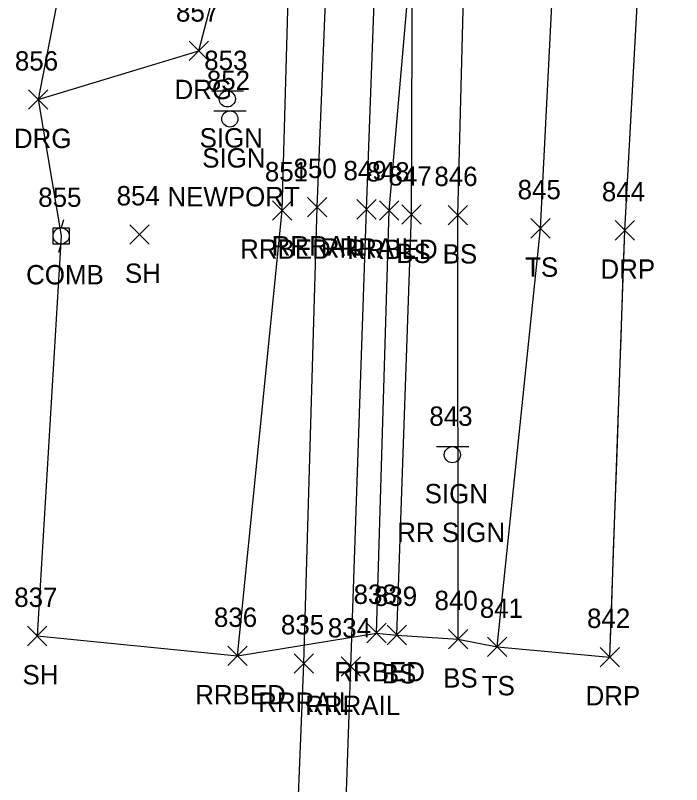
# Model space of a CAD drawing. Extents: x 1715662 to 1717487, y 887396 to 890004.
# Drawn here: x 1716428.2 to 1716497, y 887898 to 887977.4 of the extents above; entities that cross this region are included whole.
import ezdxf

# ---------------------------------------------------------------- set-up
doc = ezdxf.new("R2010")
doc.units = 0
for name, color, linetype in [('L_A', 7, 'Continuous'), ('L_I', 7, 'Continuous'), ('L_TIC', 7, 'Continuous'), ('LELB', 7, 'Continuous'), ('LSOGP', 7, 'Continuous'), ('R_A', 7, 'Continuous'), ('R_I', 7, 'Continuous'), ('R_TIC', 7, 'Continuous'), ('RDG', 7, 'Continuous'), ('RDP', 7, 'Continuous'), ('RR', 7, 'Continuous'), ('RRB', 7, 'Continuous'), ('S_A', 7, 'Continuous'), ('S_C', 7, 'Continuous'), ('S_I', 7, 'Continuous'), ('SSGN', 7, 'Continuous'), ('U_A', 7, 'Continuous'), ('U_I', 7, 'Continuous'), ('UP', 7, 'Continuous')]:
    doc.layers.add(name, color=color, linetype=linetype)

msp = doc.modelspace()

# ---------------------------------------------------------------- linework, layer by layer
at = {"layer": 'L_TIC'}
for points in [[(1716468.101, 887955.83), (1716470.101, 887957.83)], [(1716470.101, 887955.83), (1716468.101, 887957.83)], [(1716472.886, 887955.779), (1716474.886, 887957.779)], [(1716474.886, 887955.779), (1716472.886, 887957.779)], [(1716481.429, 887954.414), (1716483.429, 887956.414)], [(1716483.429, 887954.414), (1716481.429, 887956.414)], [(1716440.018, 887953.781), (1716442.018, 887955.781)], [(1716442.018, 887953.781), (1716440.018, 887955.781)], [(1716429.444, 887912.327), (1716431.444, 887914.327)], [(1716431.444, 887912.327), (1716429.444, 887914.327)], [(1716466.596, 887912.429), (1716468.596, 887914.429)], [(1716468.596, 887912.429), (1716466.596, 887914.429)], [(1716472.935, 887911.997), (1716474.935, 887913.997)], [(1716474.935, 887911.997), (1716472.935, 887913.997)], [(1716476.957, 887911.196), (1716478.957, 887913.196)], [(1716478.957, 887911.196), (1716476.957, 887913.196)]]:
    msp.add_lwpolyline(points, dxfattribs=at)
at = {"layer": 'LELB'}
for points in [[(1716473.935, 887912.997), (1716473.886, 887956.779), (1716474.684, 887987.259), (1716479.04, 888013.684), (1716476.318, 888035.409), (1716482.255, 888066.146), (1716480.224, 888093.78), (1716481.354, 888116.759), (1716483.546, 888136.5), (1716484.284, 888166.833)], [(1716467.596, 887913.429), (1716469.101, 887956.83), (1716469.216, 887985.005), (1716470.422, 888014.281), (1716470.937, 888035.677), (1716470.666, 888066.826)], [(1716477.957, 887912.196), (1716482.429, 887955.414), (1716483.839, 887983.248), (1716484.191, 888013.31), (1716484.915, 888034.821), (1716482.255, 888066.146)]]:
    msp.add_lwpolyline(points, dxfattribs=at)
at = {"layer": 'LSOGP'}
msp.add_lwpolyline([(1716434.424, 887988.776), (1716430.567, 887968.704), (1716432.923, 887954.625), (1716430.445, 887913.326), (1716451.125, 887911.268), (1716465.492, 887913.635), (1716467.599, 887913.425), (1716473.937, 887912.992), (1716477.96, 887912.2), (1716489.598, 887911.149), (1716489.79, 887916.656), (1716489.981, 887922.163), (1716490.173, 887927.67), (1716490.365, 887933.177), (1716490.556, 887938.684), (1716490.748, 887944.191), (1716490.94, 887949.698), (1716491.131, 887955.205), (1716491.515, 887962.117), (1716491.899, 887969.03), (1716492.284, 887975.943), (1716492.668, 887982.855)], dxfattribs=at)
at = {"layer": 'R_TIC'}
for points in [[(1716446.147, 887972.755), (1716448.147, 887974.755)], [(1716448.147, 887972.755), (1716446.147, 887974.755)], [(1716429.565, 887967.701), (1716431.565, 887969.701)], [(1716431.565, 887967.701), (1716429.565, 887969.701)], [(1716454.759, 887956.269), (1716456.759, 887958.269)], [(1716456.759, 887956.269), (1716454.759, 887958.269)], [(1716458.375, 887956.606), (1716460.375, 887958.606)], [(1716460.375, 887956.606), (1716458.375, 887958.606)], [(1716463.449, 887956.376), (1716465.449, 887958.376)], [(1716465.449, 887956.376), (1716463.449, 887958.376)], [(1716465.807, 887956.247), (1716467.807, 887958.247)], [(1716467.807, 887956.247), (1716465.807, 887958.247)], [(1716490.13, 887954.207), (1716492.13, 887956.207)], [(1716492.13, 887954.207), (1716490.13, 887956.207)], [(1716464.489, 887912.634), (1716466.489, 887914.634)], [(1716466.489, 887912.634), (1716464.489, 887914.634)], [(1716450.122, 887910.264), (1716452.122, 887912.264)], [(1716452.122, 887910.264), (1716450.122, 887912.264)], [(1716488.596, 887910.153), (1716490.596, 887912.153)], [(1716490.596, 887910.153), (1716488.596, 887912.153)], [(1716456.985, 887909.493), (1716458.985, 887911.493)], [(1716458.985, 887909.493), (1716456.985, 887911.493)], [(1716461.83, 887909.171), (1716463.83, 887911.171)], [(1716463.83, 887909.171), (1716461.83, 887911.171)]]:
    msp.add_lwpolyline(points, dxfattribs=at)
at = {"layer": 'RDG'}
msp.add_lwpolyline([(1716430.565, 887968.701), (1716447.147, 887973.755), (1716451.126, 887989.049), (1716451.206, 888015.403), (1716452.793, 888038.08), (1716450.596, 888065.72), (1716449.432, 888091.878), (1716428.67, 888089.543)], dxfattribs=at)
at = {"layer": 'RDP'}
msp.add_lwpolyline([(1716489.596, 887911.153), (1716491.13, 887955.207), (1716492.666, 887982.856), (1716493.215, 888012.901), (1716493.045, 888035.082), (1716494.671, 888064.725)], dxfattribs=at)
at = {"layer": 'RR'}
for points in [[(1716461.974, 887885.395), (1716462.83, 887910.171), (1716464.449, 887957.376), (1716465.442, 887984.3), (1716466.282, 888014.511), (1716466.758, 888036.126), (1716467.795, 888066.641), (1716468.474, 888094.515), (1716469.094, 888116.578), (1716469.786, 888136.617), (1716470.876, 888167.552), (1716471.475, 888180.714), (1716472.375, 888199.713), (1716473.429, 888217.51), (1716474.73, 888238.997), (1716477.211, 888271.313), (1716478.99, 888290.556), (1716481.768, 888315.217), (1716484.181, 888333.138), (1716487.83, 888360.815), (1716492.094, 888386.989), (1716497.003, 888416.355)], [(1716440.969, 887401.259), (1716441.928, 887429.633), (1716442.727, 887457.662), (1716443.78, 887486.944), (1716444.743, 887516.479), (1716445.823, 887546.3), (1716446.812, 887576.054), (1716447.839, 887605.656), (1716448.734, 887635.174), (1716449.755, 887664.736), (1716450.806, 887693.868), (1716451.722, 887723.384), (1716452.665, 887753.08), (1716453.616, 887781.945), (1716454.514, 887808.71), (1716455.264, 887837.152), (1716456.132, 887864.63), (1716456.985, 887885.763), (1716457.985, 887910.493), (1716459.375, 887957.606), (1716460.393, 887983.057)]]:
    msp.add_lwpolyline(points, dxfattribs=at)
at = {"layer": 'RRB'}
for points in [[(1716451.122, 887911.264), (1716455.759, 887957.269), (1716456.57, 887986.491), (1716457.287, 888015.179), (1716457.426, 888037.571), (1716455.225, 888065.723), (1716453.695, 888095.105), (1716450.491, 888116.185), (1716448.524, 888137.034), (1716442.327, 888164.475), (1716438.205, 888182.393), (1716431.513, 888203.116)], [(1716465.489, 887913.634), (1716466.807, 887957.247), (1716469.216, 887985.005), (1716468.759, 888014.221), (1716469.282, 888035.906), (1716469.733, 888066.764), (1716471.504, 888094.677)]]:
    msp.add_lwpolyline(points, dxfattribs=at)
at = {"layer": 'SSGN'}
for p, q in [((1716448.436, 887969.61), (1716451.769, 887969.61)), ((1716450.083, 887968.776), (1716450.083, 887968.776)), ((1716448.705, 887967.54), (1716452.038, 887967.54)), ((1716450.351, 887966.707), (1716450.351, 887966.707)), ((1716471.682, 887932.876), (1716475.015, 887932.876)), ((1716473.329, 887932.042), (1716473.329, 887932.042))]:
    msp.add_line(p, q, dxfattribs=at)
for centre in [(1716450.083, 887968.776), (1716450.351, 887966.707), (1716473.329, 887932.042)]:
    msp.add_circle(centre, 0.833, dxfattribs=at)
at = {"layer": 'UP'}
for p, q in [((1716433.17, 887956.296), (1716432.92, 887955.462)), ((1716432.087, 887953.796), (1716432.087, 887955.462)), ((1716432.087, 887955.462), (1716433.754, 887955.462)), ((1716433.754, 887955.462), (1716433.754, 887953.796)), ((1716432.92, 887954.629), (1716432.92, 887954.629)), ((1716433.754, 887953.796), (1716432.087, 887953.796)), ((1716432.67, 887952.962), (1716432.92, 887953.796))]:
    msp.add_line(p, q, dxfattribs=at)
msp.add_circle((1716432.92, 887954.629), 0.833, dxfattribs=at)

# ---------------------------------------------------------------- texts
at = {"layer": 'L_A'}
for s, p in [('BS', (1716467.541, 887951.83)), ('BS', (1716472.327, 887951.779)), ('TS', (1716480.839, 887950.414)), ('SH', (1716439.506, 887949.781)), ('SH', (1716428.932, 887908.327)), ('BS', (1716466.037, 887908.429)), ('BS', (1716472.376, 887907.997)), ('TS', (1716476.367, 887907.196))]:
    msp.add_text(s, height=2, dxfattribs=at).set_placement(p)
at = {"layer": 'L_I'}
for s, p in [('847', (1716466.738, 887959.83)), ('846', (1716471.469, 887959.779)), ('845', (1716480.067, 887958.414)), ('854', (1716438.655, 887957.781)), ('837', (1716428.082, 887916.327)), ('839', (1716465.226, 887916.429)), ('840', (1716471.486, 887915.997)), ('841', (1716476.162, 887915.196))]:
    msp.add_text(s, height=2, dxfattribs=at).set_placement(p)
at = {"layer": 'R_A'}
for s, p in [('DRG', (1716444.635, 887968.755)), ('DRG', (1716428.053, 887963.701)), ('RRBED', (1716451.405, 887952.269)), ('RRRAIL', (1716454.666, 887952.606)), ('RRRAIL', (1716459.74, 887952.376)), ('RRBED', (1716462.453, 887952.247)), ('DRP', (1716488.618, 887950.207)), ('RRBED', (1716461.135, 887908.634)), ('RRBED', (1716446.768, 887906.264)), ('DRP', (1716487.084, 887906.153)), ('RRRAIL', (1716453.276, 887905.493)), ('RRRAIL', (1716458.122, 887905.171))]:
    msp.add_text(s, height=2, dxfattribs=at).set_placement(p)
at = {"layer": 'R_I'}
for s, p in [('857', (1716444.784, 887976.755)), ('856', (1716428.148, 887971.701)), ('850', (1716456.926, 887960.606)), ('851', (1716453.964, 887960.269)), ('849', (1716462.079, 887960.376)), ('848', (1716464.445, 887960.247)), ('844', (1716488.768, 887958.207)), ('838', (1716463.127, 887916.634)), ('836', (1716448.705, 887914.264)), ('842', (1716487.234, 887914.153)), ('835', (1716455.622, 887913.493)), ('834', (1716460.468, 887913.171))]:
    msp.add_text(s, height=2, dxfattribs=at).set_placement(p)
at = {"layer": 'S_A'}
for p in [(1716447.221, 887963.756), (1716447.489, 887961.687), (1716470.467, 887927.022)]:
    msp.add_text('SIGN', height=2, dxfattribs=at).set_placement(p)
at = {"layer": 'S_C'}
for s, p in [('NEWPORT', (1716443.899, 887957.687)), ('RR SIGN', (1716467.632, 887923.022))]:
    msp.add_text(s, height=2, dxfattribs=at).set_placement(p)
at = {"layer": 'S_I'}
for s, p in [('853', (1716447.701, 887971.756)), ('852', (1716447.97, 887969.687)), ('843', (1716470.947, 887935.022))]:
    msp.add_text(s, height=2, dxfattribs=at).set_placement(p)
at = {"layer": 'U_A'}
msp.add_text('COMB', height=2, dxfattribs=at).set_placement((1716429.306, 887949.629))
at = {"layer": 'U_I'}
msp.add_text('855', height=2, dxfattribs=at).set_placement((1716430.558, 887957.629))

doc.saveas('drawing.dxf')
